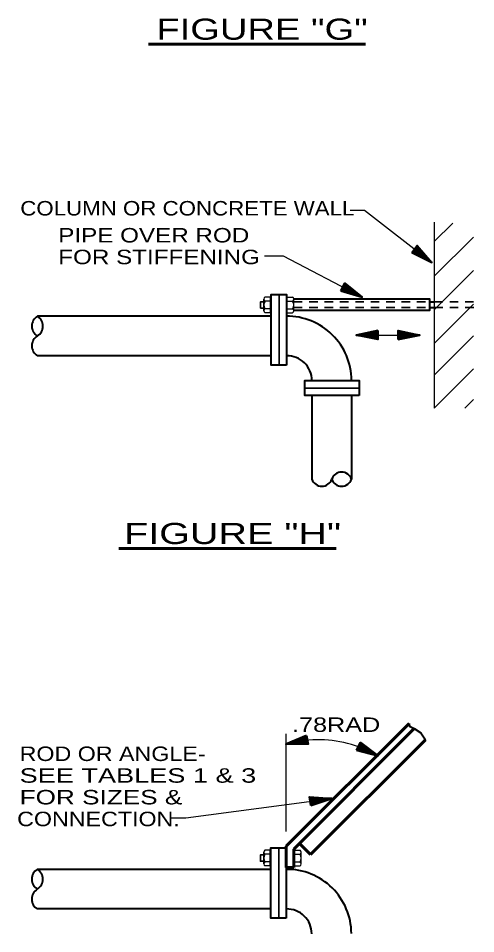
# Model space of a CAD drawing. Extents: x 55 to 190, y 198 to 264.
# Drawn here: x 78.69 to 86.71, y 219.23 to 235.3 of the extents above; entities that cross this region are included whole.
import ezdxf
from ezdxf.enums import TextEntityAlignment as Align

# ---------------------------------------------------------------- set-up
doc = ezdxf.new("R2010")
doc.units = 0
doc.header["$LTSCALE"] = 0.1
doc.linetypes.add('SHORT_DASHED', pattern=[2.7, 1.5, -1.2])
doc.layers.add('2', color=7, linetype='Continuous', lineweight=40)

msp = doc.modelspace()

# ---------------------------------------------------------------- linework, layer by layer
at = {"layer": '2', "lineweight": 60}
for p, q in [((80.9721, 234.8467), (84.7803, 234.8467)), ((80.4543, 225.9962), (84.2625, 225.9962)), ((83.3907, 220.7735), (85.5439, 222.9259)), ((83.5203, 220.719), (85.6359, 222.8339)), ((83.8156, 220.6256), (85.8299, 222.6399)), ((83.3907, 220.3949), (83.3907, 220.7735)), ((83.8159, 220.6256), (83.6214, 220.8201)), ((83.5203, 220.3949), (83.5203, 220.719)), ((83.3907, 220.3949), (83.5201, 220.3949))]:
    msp.add_line(p, q, dxfattribs=at)
at = {"layer": '2', "lineweight": 25}
for p, q in [((85.9868, 231.7199), (85.9868, 228.4576)), ((82.9975, 230.1678), (82.9975, 230.3721)), ((83.1131, 230.4062), (83.0189, 230.4062)), ((83.1131, 230.1335), (83.1131, 230.4062)), ((83.4063, 230.1335), (83.4063, 230.4062)), ((83.4063, 230.4062), (83.5005, 230.4062)), ((83.5219, 230.1678), (83.5219, 230.3721)), ((83.1131, 230.3382), (83.0181, 230.3382)), ((83.4063, 230.3382), (83.5013, 230.3382)), ((83.1131, 230.2012), (83.0181, 230.2012)), ((83.1131, 230.1335), (83.0181, 230.1335)), ((83.4063, 230.2012), (83.5013, 230.2012)), ((83.4063, 230.1335), (83.5013, 230.1335)), ((84.6157, 229.7416), (85.733, 229.7416)), ((83.3878, 221.0273), (83.3878, 222.7426)), ((82.9951, 220.4597), (82.9951, 220.664)), ((83.1107, 220.6301), (83.0158, 220.6301)), ((83.1107, 220.6981), (83.0166, 220.6981)), ((83.1107, 220.4254), (83.1107, 220.6981)), ((83.5375, 220.4254), (83.5375, 220.6981)), ((83.5375, 220.6981), (83.6317, 220.6981)), ((83.5375, 220.6301), (83.6325, 220.6301)), ((83.6531, 220.4597), (83.6531, 220.664)), ((83.1107, 220.4931), (83.0158, 220.4931)), ((83.1107, 220.4254), (83.0158, 220.4254)), ((83.5375, 220.4931), (83.6325, 220.4931)), ((83.5375, 220.4254), (83.6325, 220.4254))]:
    msp.add_line(p, q, dxfattribs=at)
at = {"layer": '2', "lineweight": 13}
for p, q in [((85.9868, 231.3807), (86.313, 231.7069)), ((85.9868, 230.7714), (86.6749, 231.4595)), ((85.9868, 230.1858), (86.6749, 230.874)), ((85.9868, 229.5953), (86.6749, 230.2835)), ((85.9868, 229.0383), (86.6749, 229.7265)), ((85.9868, 228.4576), (86.6749, 229.1457)), ((86.5239, 228.4568), (86.6749, 228.6079))]:
    msp.add_line(p, q, dxfattribs=at)
at = {"layer": '2'}
for p, q in [((85.9423, 231.0161), (85.6052, 231.2053)), ((85.9423, 231.0161), (85.6179, 231.2225)), ((85.9423, 231.0161), (85.6288, 231.2357)), ((85.6394, 231.25), (85.9423, 231.0161)), ((85.9423, 231.0161), (85.6513, 231.2648)), ((85.9423, 231.0161), (85.6743, 231.2944)), ((84.7234, 230.4068), (84.358, 230.533)), ((84.7234, 230.4068), (84.3672, 230.5523)), ((84.7234, 230.4068), (84.3757, 230.5671)), ((84.3836, 230.583), (84.7234, 230.4068)), ((84.7234, 230.4068), (84.3929, 230.5999)), ((84.7234, 230.4068), (84.4101, 230.633)), ((85.8995, 230.3229), (85.9865, 230.3229)), ((85.8995, 230.2229), (85.9873, 230.2229)), ((83.124, 230.0721), (79.0256, 230.0721)), ((84.6157, 229.7416), (84.998, 229.7985)), ((84.6157, 229.7416), (84.9985, 229.7771)), ((84.6157, 229.7416), (84.998, 229.7599)), ((84.9983, 229.7421), (84.6157, 229.7416)), ((84.6157, 229.7416), (84.998, 229.6855)), ((84.6157, 229.7416), (84.998, 229.7228)), ((85.733, 229.7416), (85.3502, 229.7061)), ((85.3504, 229.7411), (85.733, 229.7416)), ((85.733, 229.7416), (85.3507, 229.7977)), ((85.733, 229.7416), (85.3507, 229.7604)), ((85.733, 229.7416), (85.3507, 229.7233)), ((85.733, 229.7416), (85.3507, 229.6847)), ((83.124, 229.3773), (79.0256, 229.3773)), ((83.8402, 228.679), (83.8402, 227.2117)), ((84.5347, 228.679), (84.5347, 227.2117)), ((83.3849, 222.5626), (83.7489, 222.6931)), ((83.3849, 222.5626), (83.7537, 222.6722)), ((83.3849, 222.5626), (83.7563, 222.6555)), ((83.76, 222.6383), (83.3849, 222.5626)), ((83.3849, 222.5626), (83.7637, 222.619)), ((83.3849, 222.5626), (83.7709, 222.5828)), ((85.0014, 222.3563), (84.6496, 222.5071)), ((84.6572, 222.5235), (85.0014, 222.3563)), ((85.0014, 222.3563), (84.6657, 222.5407)), ((85.0014, 222.3563), (84.6824, 222.574)), ((85.0014, 222.3563), (84.6326, 222.473)), ((85.0014, 222.3563), (84.6416, 222.4923)), ((84.1889, 221.6096), (83.8024, 221.6147)), ((84.1889, 221.6096), (83.8074, 221.5776)), ((83.8098, 221.5586), (84.1889, 221.6096)), ((84.1889, 221.6096), (83.8124, 221.5408)), ((84.1889, 221.6096), (83.814, 221.5239)), ((84.1889, 221.6096), (83.8174, 221.5027)), ((83.1216, 220.364), (79.0232, 220.364)), ((83.1216, 219.6692), (79.0232, 219.6692))]:
    msp.add_line(p, q, dxfattribs=at)
at = {"layer": '2', "lineweight": 35}
for p, q in [((83.2629, 230.452), (83.2629, 229.213)), ((83.7172, 228.8113), (84.671, 228.8113)), ((83.2605, 220.7439), (83.2605, 219.5049))]:
    msp.add_line(p, q, dxfattribs=at)
at = {"layer": '2', "linetype": 'SHORT_DASHED', "lineweight": 35}
for p, q in [((83.5219, 230.3229), (85.8995, 230.3229)), ((83.5219, 230.2229), (85.8995, 230.2229)), ((85.9865, 230.3229), (86.7123, 230.3229)), ((85.9873, 230.2229), (86.7123, 230.2229))]:
    msp.add_line(p, q, dxfattribs=at)
at = {"layer": '2', "lineweight": 25}
for points in [[(84.5138, 231.9302), (84.7615, 231.9302), (85.9423, 231.0161)], [(83.0094, 231.1304), (83.3332, 231.1304), (84.7234, 230.4068)], [(81.3748, 221.2686), (81.6307, 221.2686), (84.1889, 221.6096)]]:
    msp.add_lwpolyline(points, dxfattribs=at)
at = {"layer": '2'}
for points in [[(85.5933, 231.1899), (85.6873, 231.3108), (85.9423, 231.0161)], [(85.5933, 231.1899), (85.9423, 231.0161), (85.6626, 231.2802)], [(84.349, 230.5158), (84.4199, 230.6512), (84.7234, 230.4068)], [(84.349, 230.5158), (84.7234, 230.4068), (84.4014, 230.6168)], [(83.5219, 230.3787), (85.9002, 230.3787), (85.9002, 230.1705), (83.5219, 230.1705)], [(84.998, 229.8178), (84.9978, 229.6649), (84.6157, 229.7416)], [(84.998, 229.8178), (84.6157, 229.7416), (84.9983, 229.704)], [(85.3507, 229.6654), (85.733, 229.7416), (85.3504, 229.7792)], [(85.3507, 229.6654), (85.351, 229.8183), (85.733, 229.7416)], [(85.5439, 222.9259), (85.5528, 222.8775), (85.6359, 222.8339), (85.7492, 222.7577), (85.8299, 222.6399)], [(83.7452, 222.7122), (83.7746, 222.5619), (83.3849, 222.5626)], [(83.7452, 222.7122), (83.3849, 222.5626), (83.7677, 222.6008)], [(84.6244, 222.455), (84.6914, 222.5931), (85.0014, 222.3563)], [(84.6244, 222.455), (85.0014, 222.3563), (84.6739, 222.5579)], [(83.8198, 221.4834), (83.8, 221.6353), (84.1889, 221.6096)], [(83.8198, 221.4834), (84.1889, 221.6096), (83.8047, 221.5964)]]:
    msp.add_lwpolyline(points, dxfattribs=at)
for points in [[(83.3931, 229.213), (83.124, 229.213), (83.124, 230.452), (83.3931, 230.452)], [(84.671, 228.679), (83.7172, 228.679), (83.7172, 228.942), (84.671, 228.942)], [(83.3907, 219.5049), (83.1216, 219.5049), (83.1216, 220.7439), (83.3907, 220.7439)]]:
    msp.add_lwpolyline(points, close=True, dxfattribs=at)
at = {"layer": '2', "lineweight": 35}
for points in [[(82.997, 230.3261), (82.9396, 230.3261), (82.9396, 230.2141), (82.997, 230.2141)], [(82.9946, 220.618), (82.9372, 220.618), (82.9372, 220.506), (82.9946, 220.506)]]:
    msp.add_lwpolyline(points, dxfattribs=at)
at = {"layer": '2', "lineweight": 25}
for centre, radius, start, end in [((83.0359, 230.372), 0.0382, 116.78269, 241.8391), ((83.4835, 230.372), 0.0382, 298.1609, 63.21731), ((83.1235, 230.2696), 0.126, 147.00616, 212.94297), ((83.3959, 230.2696), 0.126, 327.05703, 32.99384), ((83.0356, 230.1674), 0.0382, 117.8877, 242.03419), ((83.4838, 230.1674), 0.0382, 297.96581, 62.1123), ((83.9465, 220.5294), 2.1095, 75.77293, 105.44174), ((83.9465, 220.5294), 2.1095, 60.00147, 75.77286), ((83.1211, 220.5615), 0.126, 147.00616, 212.94297), ((83.0335, 220.6639), 0.0382, 116.78269, 241.8391), ((83.6147, 220.6639), 0.0382, 298.1609, 63.21731), ((83.5271, 220.5615), 0.126, 327.05703, 32.99384), ((83.0332, 220.4593), 0.0382, 117.8877, 242.03419), ((83.615, 220.4593), 0.0382, 297.96581, 62.1123)]:
    msp.add_arc(centre, radius, start, end, dxfattribs=at)
at = {"layer": '2'}
for centre, radius, start, end in [((79.1306, 229.8984), 0.203, 121.17154, 238.82938), ((78.9205, 229.8984), 0.203, 301.17062, 58.82846), ((83.403, 228.9401), 1.1318, 0.36422, 90.5045), ((79.1306, 229.551), 0.203, 121.17062, 238.82846), ((83.403, 228.9401), 0.4371, 0.36665, 91.08459), ((84.3609, 227.1516), 0.1837, 19.09589, 160.90477), ((84.0138, 227.2717), 0.1837, 199.09589, 340.90477), ((84.3609, 227.2717), 0.1837, 199.09523, 340.90411), ((79.1283, 220.1903), 0.203, 121.17154, 238.82938), ((78.9181, 220.1903), 0.203, 301.17062, 58.82846), ((83.4006, 219.232), 1.1318, 0.36422, 90.5045), ((79.1283, 219.8429), 0.203, 121.17062, 238.82846), ((83.4006, 219.232), 0.4371, 0.36665, 91.08459)]:
    msp.add_arc(centre, radius, start, end, dxfattribs=at)

# ---------------------------------------------------------------- texts
for s, height, width, p in [('FIGURE "G"', 0.3704, 1.35, (82.9657, 234.9237)), ('FIGURE "H"', 0.3704, 1.4, (82.448, 226.0732)), ('.78RAD', 0.254, 1.3, (84.265, 222.7759))]:
    msp.add_text(s, height=height, dxfattribs=dict(at, width=width)).set_placement(p, align=Align.CENTER)
for s, width, p in [('COLUMN OR CONCRETE WALL', 1.15, (78.725, 231.839)), ('PIPE OVER ROD', 1.25, (79.391, 231.3654)), ('FOR STIFFENING', 1.25, (79.391, 230.9844)), ('ROD OR ANGLE-', 1.2, (78.7136, 222.2655)), ('SEE TABLES 1 & 3', 1.4, (78.7136, 221.8845)), ('FOR SIZES &', 1.35, (78.7136, 221.5035)), ('CONNECTION.', 1.2, (78.67, 221.1215))]:
    msp.add_text(s, height=0.254, dxfattribs=dict(at, width=width)).set_placement(p)

doc.saveas('drawing.dxf')
